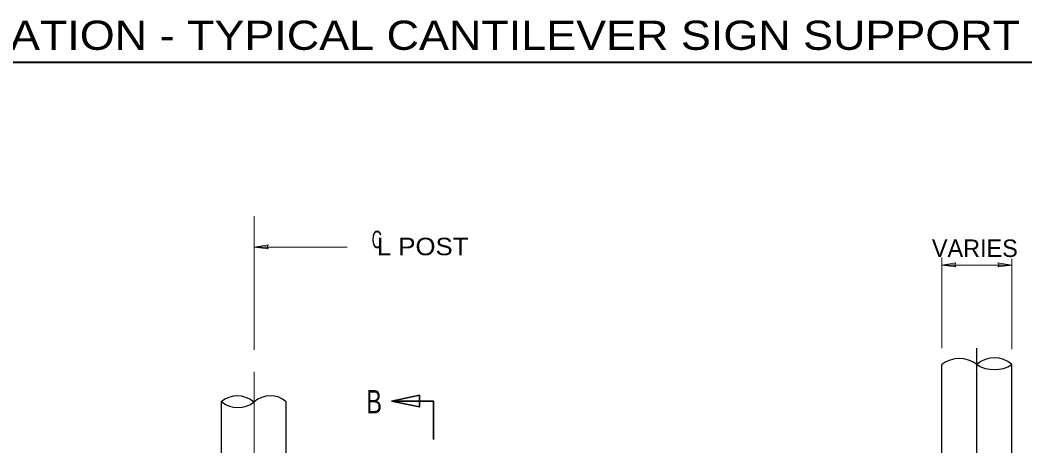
# Model space of a CAD drawing. Extents: x 312601.858 to 312602.699, y 144420.109 to 144420.704.
# Drawn here: x 312601.9631 to 312602.1364, y 144420.3709 to 144420.4438 of the extents above; entities that cross this region are included whole.
import ezdxf
from ezdxf.enums import TextEntityAlignment as Align

# ---------------------------------------------------------------- set-up
doc = ezdxf.new("R2010")
doc.units = 0
doc.header["$LTSCALE"] = 0.0012
doc.linetypes.add('LONG_DASH_SHORT_DASH', pattern=[9.9, 6, -1.2, 1.5, -1.2])
doc.linetypes.add('LONG_DASHED', pattern=[7.5, 6, -1.5])
for name, color, linetype, lineweight in [('1', 7, 'Continuous', 25), ('2', 7, 'Continuous', 25), ('39', 7, 'Continuous', 13)]:
    doc.layers.add(name, color=color, linetype=linetype, lineweight=lineweight)

msp = doc.modelspace()

# ---------------------------------------------------------------- hatches: boundary and pattern name
at = {"layer": '39'}
for points in [[(312602.0054, 144420.4049), (312602.0056, 144420.4046), (312602.0032, 144420.4049), (312602.0056, 144420.4053)], [(312602.1232, 144420.4018), (312602.1234, 144420.4015), (312602.121, 144420.4018), (312602.1234, 144420.4022)], [(312602.1308, 144420.4018), (312602.1306, 144420.4022), (312602.133, 144420.4018), (312602.1306, 144420.4015)]]:
    msp.add_hatch(color=256, dxfattribs=at).paths.add_polyline_path(points)

# ---------------------------------------------------------------- linework, layer by layer
at = {"layer": '1', "lineweight": 40}
msp.add_line((312601.9405, 144420.4366), (312602.1364, 144420.4366), dxfattribs=at)
at = {"layer": '1', "lineweight": 13}
for p, q in [((312602.0032, 144420.3873), (312602.0032, 144420.4102)), ((312602.0032, 144420.4049), (312602.0191, 144420.4049)), ((312602.121, 144420.4018), (312602.133, 144420.4018))]:
    msp.add_line(p, q, dxfattribs=at)
at = {"layer": '1', "linetype": 'LONG_DASHED'}
msp.add_line((312602.127, 144420.3603), (312602.127, 144420.3876), dxfattribs=at)
at = {"layer": '1'}
for p, q in [((312602.121, 144420.3668), (312602.121, 144420.3848)), ((312602.133, 144420.3613), (312602.133, 144420.3848)), ((312601.9976, 144420.3571), (312601.9976, 144420.3784)), ((312602.0087, 144420.3571), (312602.0087, 144420.3784))]:
    msp.add_line(p, q, dxfattribs=at)
at = {"layer": '1', "linetype": 'LONG_DASH_SHORT_DASH', "lineweight": 13}
msp.add_line((312602.0032, 144420.3623), (312602.0032, 144420.3835), dxfattribs=at)
at = {"layer": '1', "lineweight": 13}
for points in [[(312602.121, 144420.4031), (312602.121, 144420.3876), (312602.121, 144420.3877)], [(312602.133, 144420.4029), (312602.133, 144420.3876), (312602.133, 144420.3874)]]:
    msp.add_lwpolyline(points, dxfattribs=at)
at = {"layer": '1'}
for centre, radius, start, end in [((312602.123995, 144420.380886), 0.004915, 52.42867, 127.57132), ((312602.12999, 144420.381344), 0.004561, 48.91222, 131.08777), ((312602.12999, 144420.389415), 0.005518, 237.1029, 302.89711), ((312602.000306, 144420.375224), 0.004187, 48.47949, 131.52051), ((312602.005962, 144420.375228), 0.004188, 49.17791, 131.60743), ((312602.000406, 144420.381876), 0.00448, 231.71711, 308.28289)]:
    msp.add_arc(centre, radius, start, end, dxfattribs=at)
at = {"layer": '39'}
for points in [[(312602.0054, 144420.4049), (312602.0056, 144420.4046), (312602.0032, 144420.4049), (312602.0056, 144420.4053)], [(312602.1232, 144420.4018), (312602.1234, 144420.4015), (312602.121, 144420.4018), (312602.1234, 144420.4022)], [(312602.1308, 144420.4018), (312602.1306, 144420.4022), (312602.133, 144420.4018), (312602.1306, 144420.4015)], [(312602.0315, 144420.3775), (312602.0267, 144420.3785), (312602.0315, 144420.3795)]]:
    msp.add_lwpolyline(points, close=True, dxfattribs=at)
at = {"layer": '39', "lineweight": 35}
msp.add_lwpolyline([(312602.0267, 144420.3785), (312602.0315, 144420.3795), (312602.0315, 144420.3775)], close=True, dxfattribs=at)
msp.add_lwpolyline([(312602.0269, 144420.3785), (312602.0339, 144420.3785), (312602.0339, 144420.3719)], dxfattribs=at)

# ---------------------------------------------------------------- texts
at = {"layer": '1'}
msp.add_text('VARIES', height=0.003, dxfattribs=at).set_placement((312602.12665, 144420.4032), align=Align.CENTER)
at = {"layer": '1', "width": 0.75}
msp.add_text('B', height=0.004, dxfattribs=at).set_placement((312602.0224, 144420.3764))
at = {"layer": '2', "width": 1.15}
msp.add_text('ELEVATION - TYPICAL CANTILEVER SIGN SUPPORT', height=0.005, dxfattribs=at).set_placement((312601.9417, 144420.4387))
at = {"layer": '2'}
for s, width, p in [('C', 0.6, (312602.0242, 144420.4047)), ('L POST', 1.1, (312602.03205, 144420.4035))]:
    msp.add_text(s, height=0.003, dxfattribs=dict(at, width=width)).set_placement(p, align=Align.CENTER)

doc.saveas('drawing.dxf')
